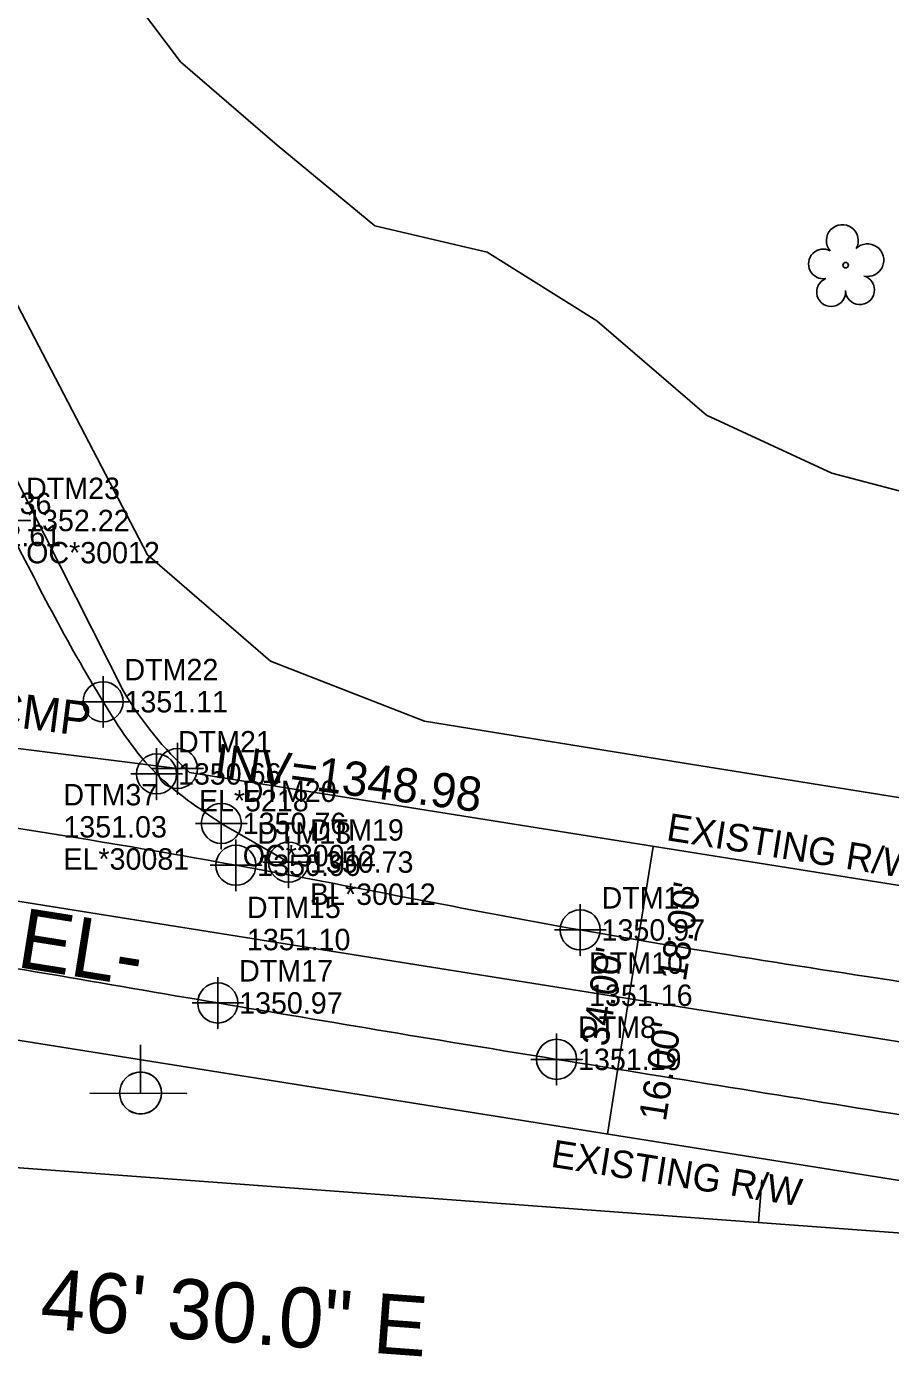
# Model space of a CAD drawing. Extents: x 1435573 to 1437263, y 981340 to 982884.
# Drawn here: x 1436441.9 to 1436542.7, y 982404.3 to 982559.5 of the extents above; entities that cross this region are included whole.
import ezdxf

# ---------------------------------------------------------------- set-up
doc = ezdxf.new("R2010")
doc.units = 0
for name, color, linetype in [('Exist DTM Crownline Cogo Comment', 7, 'Continuous'), ('Exist DTM Crownline Cogo Elevation', 7, 'Continuous'), ('Exist DTM Crownline Cogo Number', 7, 'Continuous'), ('Exist Horizontal Alignment', 7, 'Continuous'), ('Exist Horizontal Alignment Direction Label', 7, 'Continuous'), ('Exist Horizontal Baseline Alignment', 7, 'Continuous'), ('Exist Horizontal Baseline Alignment Direction Label', 7, 'Continuous'), ('Exist Horizontal Baseline Alignment Tick small', 7, 'Continuous'), ('Exist Right of Way Line', 7, 'Continuous'), ('Exist Right of Way Line Text', 7, 'Continuous'), ('Exist Right of Way Width CELL', 7, 'Continuous'), ('Exist Roads EOP', 7, 'Continuous'), ('Exist Roads EOP Cogo Comment', 7, 'Continuous'), ('Exist Roads EOP Cogo Elevation', 7, 'Continuous'), ('Exist Roads EOP Cogo Number', 7, 'Continuous'), ('Exist Roads EOP Cogo Point CELL', 7, 'Continuous'), ('Exist Structure Minor Pipes CMP 18 Inch', 7, 'Continuous'), ('Exist Structure Minor Pipes CMP 18 Inch Cogo Comment', 7, 'Continuous'), ('Exist Structure Minor Pipes CMP 18 Inch Cogo Point CELL', 7, 'Continuous'), ('Exist Structure Minor Pipes CMP 18 Inch Invert', 7, 'Continuous'), ('Exist Structure Minor Pipes CMP 18 Inch Text', 7, 'Continuous'), ('Exist Utilities Power Joint Use Telephone CELL', 7, 'Continuous'), ('Exist Utilities Power Pole CELL', 7, 'Continuous'), ('Exist Vegetation Tree CELL', 7, 'Continuous'), ('Exist Vegetation Woods Line', 7, 'Continuous')]:
    doc.layers.add(name, color=color, linetype=linetype)

# ---------------------------------------------------------------- blocks, each defined once
blk = doc.blocks.new('EXIST UTILITIES POWER POLE')
at = {"layer": 'Exist Utilities Power Pole CELL'}
for q in [(0, 0.1125), (0, 0)]:
    blk.add_line((0, 0), q, dxfattribs=at)
blk.add_circle((0, 0), 0.049, dxfattribs=at)
blk = doc.blocks.new('EXIST UTILITIES POWER JOINT USE TELEPHONE')
at = {"layer": 'Exist Utilities Power Joint Use Telephone CELL'}
blk.add_line((0, 0), (0, 0), dxfattribs=at)
blk.add_lwpolyline([(-0.1188, 0), (0.108, -0.0008), (0, -0.0004), (0, 0.1125)], dxfattribs=at)
blk.add_circle((0, 0.0001), 0.049, dxfattribs=at)

msp = doc.modelspace()

# ---------------------------------------------------------------- linework, layer by layer
at = {"layer": 'Exist Horizontal Alignment'}
msp.add_line((1436349.2, 982472.02), (1436631.57, 982427.08), dxfattribs=at)
at = {"layer": 'Exist Horizontal Baseline Alignment'}
msp.add_line((1436220.79, 982442.59), (1436692.1, 982407.77), dxfattribs=at)
at = {"layer": 'Exist Horizontal Baseline Alignment Tick small'}
msp.add_line((1436527.34, 982419.94), (1436527.71, 982424.93), dxfattribs=at)
at = {"layer": 'Exist Right of Way Line'}
for p, q in [((1436362.49, 982661.08), (1436453.17, 982481.97)), ((1436460.9, 982472.47), (1436634.4, 982444.85)), ((1436346.68, 982456.22), (1436629.05, 982411.27))]:
    msp.add_line(p, q, dxfattribs=at)
msp.add_arc((1436488.27, 982502.62), 40.72, 210.4714, 227.7645, dxfattribs=at)
at = {"layer": 'Exist Right of Way Width CELL'}
for p in [(1436515.02, 982463.85), (1436509.68, 982430.28)]:
    msp.add_line(p, (1436512.35, 982447.1), dxfattribs=at)
at = {"layer": 'Exist Roads EOP'}
msp.add_line((1436472.45, 982462.02), (1436464.6, 982466.53), dxfattribs=at)
for points in [[(1436464.6, 982466.53), (1436457.04, 982472.31), (1436450.79, 982480.73), (1436439.31, 982501.88)], [(1436464.6, 982466.53), (1436457.04, 982472.31), (1436450.79, 982480.73), (1436439.31, 982501.88)], [(1436588.99, 982441.11), (1436549.29, 982447.24), (1436506.5, 982454.1), (1436466.3, 982461.65), (1436427.31, 982468.12), (1436386.36, 982474.42), (1436348, 982479.53), (1436317.91, 982480.78), (1436294.78, 982478.72), (1436266.25, 982470.95), (1436237.24, 982453.92), (1436214.3, 982427.57)], [(1436586.86, 982425.39), (1436547.07, 982432), (1436503.75, 982439), (1436464.18, 982445.58), (1436424.48, 982452.27), (1436384.26, 982458.26), (1436345.94, 982463.43), (1436318.12, 982465.29), (1436296.64, 982463.74), (1436271.59, 982456.95), (1436246.62, 982442.88), (1436222.43, 982421.49)]]:
    msp.add_spline(points, degree=3, dxfattribs=at)
at = {"layer": 'Exist Roads EOP Cogo Point CELL'}
for points in [[(1436439.31, 982504.88), (1436439.31, 982498.88), (1436439.31, 982501.88), (1436442.31, 982501.88), (1436436.31, 982501.88)], [(1436450.79, 982483.73), (1436450.79, 982477.73), (1436450.79, 982480.73), (1436453.79, 982480.73), (1436447.79, 982480.73)], [(1436457.04, 982475.31), (1436457.04, 982469.31), (1436457.04, 982472.31), (1436460.04, 982472.31), (1436454.04, 982472.31)], [(1436464.6, 982469.53), (1436464.6, 982463.53), (1436464.6, 982466.53), (1436467.6, 982466.53), (1436461.6, 982466.53)], [(1436466.3, 982464.65), (1436466.3, 982458.65), (1436466.3, 982461.65), (1436469.3, 982461.65), (1436463.3, 982461.65)], [(1436472.45, 982465.02), (1436472.45, 982459.02), (1436472.45, 982462.02), (1436475.45, 982462.02), (1436469.45, 982462.02)], [(1436506.5, 982457.1), (1436506.5, 982451.1), (1436506.5, 982454.1), (1436509.5, 982454.1), (1436503.5, 982454.1)], [(1436464.18, 982448.58), (1436464.18, 982442.58), (1436464.18, 982445.58), (1436467.18, 982445.58), (1436461.18, 982445.58)], [(1436503.75, 982442), (1436503.75, 982436), (1436503.75, 982439), (1436506.75, 982439), (1436500.75, 982439)]]:
    msp.add_lwpolyline(points, dxfattribs=at)
for centre in [(1436450.79, 982480.73), (1436457.04, 982472.31), (1436464.6, 982466.53), (1436472.45, 982462.02), (1436466.3, 982461.65), (1436506.5, 982454.1), (1436464.18, 982445.58), (1436503.75, 982439)]:
    msp.add_circle(centre, 2.34, dxfattribs=at)
at = {"layer": 'Exist Structure Minor Pipes CMP 18 Inch'}
msp.add_line((1436404.11, 982479.91), (1436459.48, 982472.94), dxfattribs=at)
at = {"layer": 'Exist Structure Minor Pipes CMP 18 Inch Cogo Point CELL'}
msp.add_lwpolyline([(1436459.48, 982475.94), (1436459.48, 982469.94), (1436459.48, 982472.94), (1436462.48, 982472.94), (1436456.48, 982472.94)], dxfattribs=at)
msp.add_circle((1436459.48, 982472.94), 2.34, dxfattribs=at)
at = {"layer": 'Exist Vegetation Tree CELL'}
msp.add_line((1436537.5, 982531.67), (1436537.5, 982531.67), dxfattribs=at)
msp.add_circle((1436537.5, 982531.67), 0.326, dxfattribs=at)
for centre, radius, start, end in [((1436537.11, 982534.54), 1.86, 330.1651, 219.7134), ((1436534.89, 982531.82), 1.73, 62.6636, 279.3457), ((1436540.05, 982532.26), 1.9, 257.1011, 134.1999), ((1436535.8, 982528.55), 1.69, 111.5671, 6.231), ((1436539.17, 982528.77), 1.7, 181.2822, 74.56)]:
    msp.add_arc(centre, radius, start, end, dxfattribs=at)
at = {"layer": 'Exist Vegetation Woods Line'}
for points in [[(1436709.86, 982445.43), (1436673.85, 982448.35), (1436636.59, 982451.74), (1436599.44, 982457.01), (1436556.56, 982467.51), (1436518.42, 982473.6), (1436488.34, 982478.47), (1436470.36, 982485.46), (1436455.98, 982497.86), (1436419.79, 982567.3), (1436382.96, 982635.88), (1436360.99, 982683.15), (1436359.14, 982707.48), (1436368.37, 982728.89), (1436371.28, 982731.54), (1436377.82, 982727.96)], [(1436451.33, 982566.69), (1436459.82, 982555.42), (1436471.13, 982545.67), (1436482.53, 982536.25), (1436495.64, 982533.21), (1436508.43, 982525.18), (1436521.26, 982514.18), (1436535.87, 982507.4), (1436555.3, 982502.32), (1436594.72, 982490.74), (1436611.16, 982487.06), (1436630.1, 982483.94), (1436650.4, 982479.31), (1436672.55, 982476.52), (1436693.3, 982480.24)]]:
    msp.add_lwpolyline(points, dxfattribs=at)

# ---------------------------------------------------------------- block references
at = {"layer": 'Exist Utilities Power Joint Use Telephone CELL', "xscale": 50, "yscale": 50}
msp.add_blockref('EXIST UTILITIES POWER JOINT USE TELEPHONE', (1436455.17, 982435.07), dxfattribs=at)
at = {"layer": 'Exist Utilities Power Pole CELL', "xscale": 50, "yscale": 50}
msp.add_blockref('EXIST UTILITIES POWER POLE', (1436455.17, 982435.07), dxfattribs=at)

# ---------------------------------------------------------------- texts
at = {"layer": 'Exist DTM Crownline Cogo Comment'}
msp.add_text('EL*30081', height=2.5, dxfattribs=at).set_placement((1436446.16, 982461.13))
at = {"layer": 'Exist DTM Crownline Cogo Elevation'}
for s, p in [('1352.61', (1436433.81, 982498.88)), ('1351.03', (1436446.16, 982464.88)), ('1351.10', (1436467.59, 982451.73)), ('1351.16', (1436507.54, 982445.23))]:
    msp.add_text(s, height=2.5, dxfattribs=at).set_placement(p)
at = {"layer": 'Exist DTM Crownline Cogo Number'}
for s, p in [('DTM36', (1436433.81, 982502.63)), ('DTM37', (1436446.16, 982468.63)), ('DTM15', (1436467.59, 982455.48)), ('DTM10', (1436507.54, 982448.98))]:
    msp.add_text(s, height=2.5, dxfattribs=at).set_placement(p)
at = {"layer": 'Exist Horizontal Alignment Direction Label'}
msp.add_text('-EL-', height=7, rotation=350.9559, dxfattribs=at).set_placement((1436437.48, 982450.28))
at = {"layer": 'Exist Horizontal Baseline Alignment Direction Label'}
msp.add_text('S 85%%d 46\' 30.0" E', height=7, rotation=355.775, dxfattribs=at).set_placement((1436417.81, 982409.52))
at = {"layer": 'Exist Right of Way Line Text'}
for p in [(1436516.46, 982464.59), (1436502.97, 982426.48)]:
    msp.add_text('EXISTING R/W', height=3.2, rotation=350.9559, dxfattribs=at).set_placement(p)
at = {"layer": 'Exist Right of Way Width CELL'}
for s, p in [("18.00'", (1436518.82, 982447.99)), ("34.00'", (1436509.74, 982440.4)), ("16.00'", (1436516.49, 982431.66))]:
    msp.add_text(s, height=3.2, rotation=80.9559, dxfattribs=at).set_placement(p)
at = {"layer": 'Exist Roads EOP Cogo Comment'}
for s, p in [('OC*30012', (1436441.81, 982496.88)), ('OC*30012', (1436467.1, 982461.53)), ('BL*30012', (1436474.95, 982457.02))]:
    msp.add_text(s, height=2.5, dxfattribs=at).set_placement(p)
at = {"layer": 'Exist Roads EOP Cogo Elevation'}
for s, p in [('1352.22', (1436441.81, 982500.63)), ('1351.11', (1436453.29, 982479.48)), ('1350.66', (1436459.54, 982471.06)), ('1350.76', (1436467.1, 982465.28)), ('1350.90', (1436468.8, 982460.4)), ('1350.73', (1436474.95, 982460.77)), ('1350.97', (1436509, 982452.85)), ('1350.97', (1436466.68, 982444.33)), ('1351.19', (1436506.25, 982437.75))]:
    msp.add_text(s, height=2.5, dxfattribs=at).set_placement(p)
at = {"layer": 'Exist Roads EOP Cogo Number'}
for s, p in [('DTM23', (1436441.81, 982504.38)), ('DTM22', (1436453.29, 982483.23)), ('DTM21', (1436459.54, 982474.81)), ('DTM20', (1436467.1, 982469.03)), ('DTM13', (1436468.8, 982464.15)), ('DTM19', (1436474.95, 982464.52)), ('DTM12', (1436509, 982456.6)), ('DTM17', (1436466.68, 982448.08)), ('DTM8', (1436506.25, 982441.5))]:
    msp.add_text(s, height=2.5, dxfattribs=at).set_placement(p)
at = {"layer": 'Exist Structure Minor Pipes CMP 18 Inch Cogo Comment'}
msp.add_text('EL*5218', height=2.5, dxfattribs=at).set_placement((1436461.98, 982467.94))
at = {"layer": 'Exist Structure Minor Pipes CMP 18 Inch Invert'}
msp.add_text('INV=1348.98', height=4, rotation=352.5359, dxfattribs=at).set_placement((1436463.63, 982471.91))
at = {"layer": 'Exist Structure Minor Pipes CMP 18 Inch Text'}
msp.add_text('18" CMP', height=4, rotation=352.833, dxfattribs=at).set_placement((1436428.06, 982479.3))

doc.saveas('drawing.dxf')
